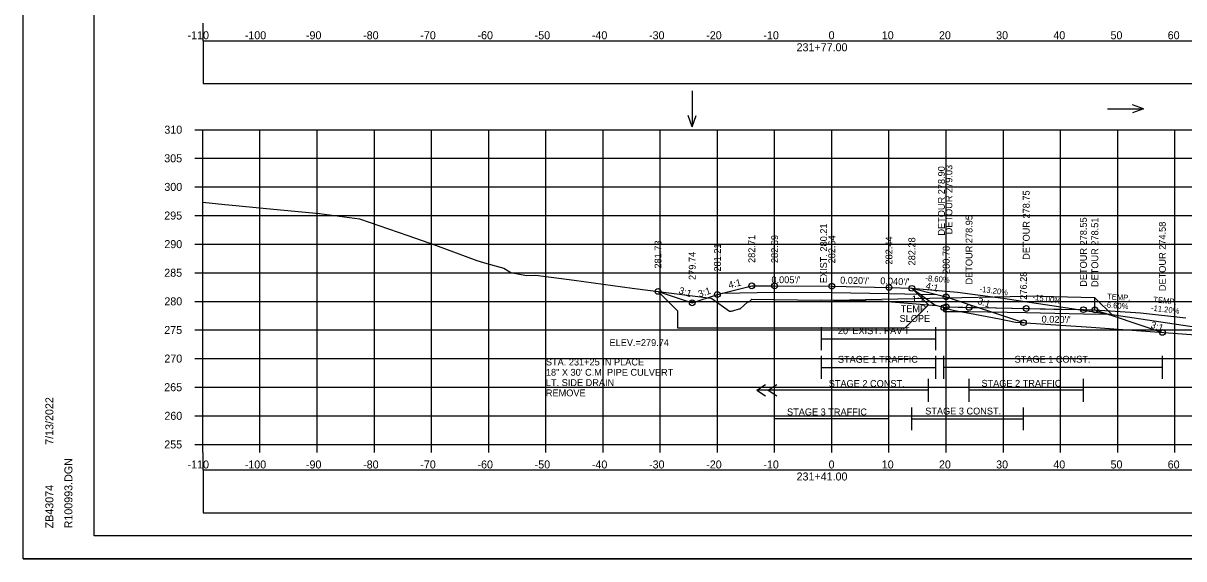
# Model space of a CAD drawing. Extents: x 4667 to 1632277, y -2100 to 724501.
# Drawn here: x 5635.8 to 5838.7, y 809.6 to 903.2 of the extents above; entities that cross this region are included whole.
import ezdxf

# ---------------------------------------------------------------- set-up
doc = ezdxf.new("R2010")
doc.units = 0
for name, color, linetype in [('R_Alt Surface', 7, 'Continuous'), ('R_Axis', 7, 'Continuous'), ('R_Axis Annot', 7, 'Continuous'), ('R_Border', 7, 'Continuous'), ('R_Border Notes', 7, 'Continuous'), ('R_Detour', 7, 'Continuous'), ('R_Detour Annot', 7, 'Continuous'), ('R_Drive', 7, 'Continuous'), ('R_Exist Surface', 7, 'Continuous'), ('R_Fin Surface', 7, 'Continuous'), ('R_Fin Surface Annot', 7, 'Continuous'), ('R_Grid', 7, 'Continuous'), ('R_No Plot', 7, 'Continuous'), ('R_Proposed CofA', 7, 'Continuous'), ('R_ROW', 7, 'Continuous'), ('R_Temp Easement', 7, 'Continuous'), ('R_Water Annot', 7, 'Continuous'), ('T_Drafting', 7, 'Continuous'), ('T_Notes', 7, 'Continuous')]:
    doc.layers.add(name, color=color, linetype=linetype)

msp = doc.modelspace()

# ---------------------------------------------------------------- linework, layer by layer
at = {"layer": 'R_Alt Surface'}
msp.add_lwpolyline([(5758.04, 856.03), (5767.18, 856.22), (5777.18, 856.17), (5787.18, 855.97), (5795.55, 855.8)], dxfattribs=at)
at = {"layer": 'R_Axis'}
for p, q in [((5665.78, 884.61), (5667.18, 884.61)), ((5667.18, 829.61), (5667.18, 884.61)), ((5665.78, 879.61), (5667.18, 879.61)), ((5665.78, 874.61), (5667.18, 874.61)), ((5665.78, 869.61), (5667.18, 869.61)), ((5665.78, 864.61), (5667.18, 864.61)), ((5665.78, 859.61), (5667.18, 859.61)), ((5665.78, 854.61), (5667.18, 854.61)), ((5665.78, 849.61), (5667.18, 849.61)), ((5665.78, 844.61), (5667.18, 844.61)), ((5665.78, 839.61), (5667.18, 839.61)), ((5665.78, 834.61), (5667.18, 834.61)), ((5665.78, 829.61), (5667.18, 829.61)), ((5667.18, 829.61), (5947.18, 829.61)), ((5667.18, 828.21), (5667.18, 829.61)), ((5677.18, 828.21), (5677.18, 829.61)), ((5687.18, 828.21), (5687.18, 829.61)), ((5697.18, 828.21), (5697.18, 829.61)), ((5707.18, 828.21), (5707.18, 829.61)), ((5717.18, 828.21), (5717.18, 829.61)), ((5727.18, 828.21), (5727.18, 829.61)), ((5737.18, 828.21), (5737.18, 829.61)), ((5747.18, 828.21), (5747.18, 829.61)), ((5757.18, 828.21), (5757.18, 829.61)), ((5767.18, 828.21), (5767.18, 829.61)), ((5777.18, 828.21), (5777.18, 829.61)), ((5787.18, 828.21), (5787.18, 829.61)), ((5797.18, 828.21), (5797.18, 829.61)), ((5807.18, 828.21), (5807.18, 829.61)), ((5817.18, 828.21), (5817.18, 829.61)), ((5827.18, 828.21), (5827.18, 829.61)), ((5837.18, 828.21), (5837.18, 829.61))]:
    msp.add_line(p, q, dxfattribs=at)
at = {"layer": 'R_Border'}
for p, q in [((5648.18, 813.61), (5648.18, 1019.07)), ((5648.18, 813.61), (5648.18, 813.61)), ((5964.36, 813.61), (5648.18, 813.61))]:
    msp.add_line(p, q, dxfattribs=at)
at = {"layer": 'R_Detour'}
for points in [[(5796.78, 852.84), (5796.78, 853.51), (5796.78, 853.51), (5796.78, 853.51), (5797.01, 853.59), (5797.18, 853.64), (5799.26, 853.6), (5801.18, 853.56), (5805.99, 853.47), (5811.18, 853.36), (5815.99, 853.27), (5821.18, 853.16), (5822.15, 853.15), (5823.18, 853.12), (5824.84, 852.57), (5826.38, 852.06), (5830.69, 850.62), (5834.99, 849.19)], [(5796.78, 852.84), (5801.17, 852.84), (5811.18, 852.64), (5821.17, 852.44), (5825.49, 852.36)]]:
    msp.add_lwpolyline(points, dxfattribs=at)
at = {"layer": 'R_Drive'}
for p, q in [((5791.18, 856.89), (5799.15, 856.2)), ((5799.15, 856.2), (5807.09, 855.16)), ((5807.09, 855.16), (5843.99, 849.62)), ((5823.18, 853.12), (5831.17, 852.6)), ((5831.17, 852.6), (5839.12, 851.71))]:
    msp.add_line(p, q, dxfattribs=at)
at = {"layer": 'R_Exist Surface'}
msp.add_lwpolyline([(5667.18, 871.94), (5671.03, 871.51), (5671.71, 871.49), (5678.32, 870.84), (5687.57, 869.98), (5694.6, 869.02), (5703.05, 866.11), (5707.86, 864.43), (5715.13, 861.76), (5716.87, 861.23), (5719.82, 860.39), (5721.04, 859.67), (5723.81, 859.12), (5725.43, 859.21), (5732.12, 858.29), (5742.29, 856.91), (5756.02, 855.17), (5756.21, 855.13), (5759.31, 852.91), (5759.33, 852.91), (5759.48, 852.92), (5759.56, 852.9), (5759.75, 852.97), (5759.88, 852.98), (5761, 853.29), (5761.15, 853.33), (5762.45, 854.44), (5762.72, 854.51), (5763.19, 855.02), (5775.13, 854.8), (5775.4, 854.85), (5779.71, 854.77), (5786.06, 854.65), (5786.15, 854.64), (5786.18, 854.62), (5791.23, 854.22), (5794.72, 853.96), (5795.36, 853.95), (5796.37, 853.63), (5796.66, 853.6), (5796.84, 853.49), (5798.65, 853.04), (5801.26, 852.54), (5806.5, 851.53), (5809.31, 850.98), (5822.54, 850.08), (5842.39, 848.66)], dxfattribs=at)
at = {"layer": 'R_Fin Surface'}
msp.add_lwpolyline([(5746.79, 856.34), (5752.77, 854.35), (5757.18, 855.82), (5758.04, 856.03), (5763.18, 857.32), (5767.18, 857.3), (5777.18, 857.25), (5787.18, 857.05), (5791.18, 856.89), (5795.55, 855.8), (5797.18, 855.39), (5810.69, 850.89)], dxfattribs=at)
at = {"layer": 'R_Grid'}
for p, q in [((5667.18, 884.61), (5947.18, 884.61)), ((5667.18, 829.61), (5667.18, 884.61)), ((5677.18, 829.61), (5677.18, 884.61)), ((5687.18, 829.61), (5687.18, 884.61)), ((5697.18, 829.61), (5697.18, 884.61)), ((5707.18, 829.61), (5707.18, 884.61)), ((5717.18, 829.61), (5717.18, 884.61)), ((5727.18, 829.61), (5727.18, 884.61)), ((5737.18, 829.61), (5737.18, 884.61)), ((5747.18, 829.61), (5747.18, 884.61)), ((5757.18, 829.61), (5757.18, 884.61)), ((5767.18, 829.61), (5767.18, 884.61)), ((5777.18, 829.61), (5777.18, 884.61)), ((5787.18, 829.61), (5787.18, 884.61)), ((5797.18, 829.61), (5797.18, 884.61)), ((5807.18, 829.61), (5807.18, 884.61)), ((5817.18, 829.61), (5817.18, 884.61)), ((5827.18, 829.61), (5827.18, 884.61)), ((5837.18, 829.61), (5837.18, 884.61)), ((5667.18, 879.61), (5947.18, 879.61)), ((5667.18, 874.61), (5947.18, 874.61)), ((5667.18, 869.61), (5947.18, 869.61)), ((5667.18, 864.61), (5947.18, 864.61)), ((5667.18, 859.61), (5947.18, 859.61)), ((5667.18, 854.61), (5947.18, 854.61)), ((5667.18, 849.61), (5947.18, 849.61)), ((5667.18, 844.61), (5947.18, 844.61)), ((5667.18, 839.61), (5947.18, 839.61)), ((5667.18, 834.61), (5947.18, 834.61)), ((5667.18, 829.61), (5947.18, 829.61))]:
    msp.add_line(p, q, dxfattribs=at)
at = {"layer": 'R_No Plot'}
for p, q in [((5667.18, 903.21), (5667.18, 900.14)), ((5791.18, 856.89), (5795.26, 853.95)), ((5667.18, 828.21), (5667.18, 825.14)), ((5635.78, 809.63), (5969.12, 809.63))]:
    msp.add_line(p, q, dxfattribs=at)
for points in [[(5635.78, 1022.97), (5969.12, 1022.97), (5969.12, 809.63), (5635.78, 809.63)], [(5882.1, 1019.07), (5901.72, 1019.07), (5901.72, 1009.19), (5917.84, 1009.19), (5941.04, 1009.19), (5941.04, 984.86), (5964.36, 984.86), (5964.36, 813.61), (5648.18, 813.61), (5648.18, 1019.07)]]:
    msp.add_lwpolyline(points, close=True, dxfattribs=at)
for centre in [(5746.79, 856.34), (5763.18, 857.32), (5767.18, 857.3), (5777.18, 857.25), (5787.18, 857.05), (5791.18, 856.89), (5752.77, 854.35), (5757.18, 855.82), (5797.18, 855.39), (5796.78, 853.51), (5797.18, 853.64), (5801.18, 853.56), (5811.18, 853.36), (5821.18, 853.16), (5823.18, 853.12), (5810.69, 850.89), (5834.99, 849.19)]:
    msp.add_circle(centre, 0.5, dxfattribs=at)
at = {"layer": 'R_Proposed CofA'}
for p, q in [((5764.07, 839.08), (5765.57, 840.08)), ((5764.07, 839.08), (5765.57, 838.08)), ((5766.07, 839.08), (5767.57, 840.08)), ((5766.07, 839.08), (5767.57, 838.08))]:
    msp.add_line(p, q, dxfattribs=at)
for points in [[(5667.23, 892.67), (5947.13, 892.67), (5947.13, 900.09), (5667.23, 900.09)], [(5667.23, 817.67), (5947.13, 817.67), (5947.13, 825.09), (5667.23, 825.09)]]:
    msp.add_lwpolyline(points, close=True, dxfattribs=at)
at = {"layer": 'R_ROW'}
for p, q in [((5746.79, 856.34), (5750.23, 852.9)), ((5750.27, 852.9), (5750.23, 852.9)), ((5750.27, 849.9), (5750.27, 852.9)), ((5794.07, 854.01), (5789.96, 849.9)), ((5789.96, 849.9), (5750.27, 849.9))]:
    msp.add_line(p, q, dxfattribs=at)
at = {"layer": 'R_Temp Easement'}
for p, q in [((5775.37, 846.08), (5775.37, 850.08)), ((5795.37, 846.08), (5795.37, 850.08)), ((5775.37, 848.08), (5795.37, 848.08)), ((5775.37, 841.08), (5775.37, 845.08)), ((5795.37, 841.08), (5795.37, 845.08)), ((5796.78, 841.08), (5796.78, 845.08)), ((5834.99, 841.08), (5834.99, 845.08)), ((5775.37, 843.08), (5795.37, 843.08)), ((5834.99, 843.08), (5796.78, 843.08)), ((5794.07, 837.08), (5794.07, 841.08)), ((5801.18, 837.08), (5801.18, 841.08)), ((5821.18, 837.08), (5821.18, 841.08)), ((5794.07, 839.08), (5764.07, 839.08)), ((5821.18, 839.08), (5801.18, 839.08)), ((5767.18, 832.08), (5767.18, 836.08)), ((5787.18, 832.08), (5787.18, 836.08)), ((5791.18, 832.08), (5791.18, 836.08)), ((5810.69, 832.08), (5810.69, 836.08)), ((5787.18, 834.08), (5767.18, 834.08)), ((5791.18, 834.08), (5810.69, 834.08))]:
    msp.add_line(p, q, dxfattribs=at)
at = {"layer": 'R_Water Annot'}
for p, q in [((5752.77, 891.42), (5752.77, 885.13)), ((5831.68, 888.27), (5829.75, 888.97)), ((5752.77, 885.13), (5752.07, 887.06)), ((5752.77, 885.13), (5753.47, 887.06)), ((5825.39, 888.27), (5831.68, 888.27)), ((5831.68, 888.27), (5829.75, 887.57))]:
    msp.add_line(p, q, dxfattribs=at)
at = {"layer": 'T_Drafting'}
msp.add_line((5791.18, 856.89), (5794.07, 854.01), dxfattribs=at)
at = {"layer": 'T_Notes'}
for p, q in [((5777.49, 854.81), (5811.18, 855.49)), ((5823.18, 855.25), (5811.18, 855.49)), ((5823.18, 853.12), (5823.18, 855.25)), ((5823.18, 855.25), (5826.37, 852.06)), ((5797.18, 853.64), (5823.18, 853.12)), ((5823.18, 853.12), (5826.37, 852.06))]:
    msp.add_line(p, q, dxfattribs=at)
msp.add_lwpolyline([(5777.49, 854.81), (5786.06, 854.65), (5786.15, 854.64), (5786.18, 854.62), (5791.23, 854.22), (5794.72, 853.96), (5795.36, 853.95), (5796.37, 853.63), (5796.66, 853.6), (5796.8, 853.52), (5797.18, 853.64)], dxfattribs=at)

# ---------------------------------------------------------------- texts
at = {"layer": 'R_Axis Annot'}
for s, p in [('-110', (5664.52, 900.41)), ('-100', (5674.52, 900.41)), ('-90', (5685.22, 900.41)), ('-80', (5695.22, 900.41)), ('-70', (5705.22, 900.41)), ('-60', (5715.22, 900.41)), ('-50', (5725.22, 900.41)), ('-40', (5735.22, 900.41)), ('-30', (5745.22, 900.41)), ('-20', (5755.22, 900.41)), ('-10', (5765.22, 900.41)), ('0', (5776.62, 900.41)), ('10', (5785.92, 900.41)), ('20', (5795.92, 900.41)), ('30', (5805.92, 900.41)), ('40', (5815.92, 900.41)), ('50', (5825.92, 900.41)), ('60', (5835.92, 900.41)), ('231+77.00', (5771.02, 898.31)), ('310', (5660.46, 883.91)), ('305', (5660.44, 878.91)), ('300', (5660.46, 873.91)), ('295', (5660.44, 868.91)), ('290', (5660.46, 863.91)), ('285', (5660.44, 858.91)), ('280', (5660.46, 853.91)), ('275', (5660.44, 848.91)), ('270', (5660.46, 843.91)), ('265', (5660.44, 838.91)), ('260', (5660.46, 833.91)), ('255', (5660.44, 828.91)), ('-110', (5664.52, 825.41)), ('-100', (5674.52, 825.41)), ('-90', (5685.22, 825.41)), ('-80', (5695.22, 825.41)), ('-70', (5705.22, 825.41)), ('-60', (5715.22, 825.41)), ('-50', (5725.22, 825.41)), ('-40', (5735.22, 825.41)), ('-30', (5745.22, 825.41)), ('-20', (5755.22, 825.41)), ('-10', (5765.22, 825.41)), ('0', (5776.62, 825.41)), ('10', (5785.92, 825.41)), ('20', (5795.92, 825.41)), ('30', (5805.92, 825.41)), ('40', (5815.92, 825.41)), ('50', (5825.92, 825.41)), ('60', (5835.92, 825.41)), ('231+41.00', (5771.02, 823.31))]:
    msp.add_text(s, height=1.4, dxfattribs=at).set_placement(p)
at = {"layer": 'R_Border'}
for s, p in [('7/13/2022', (5641.05, 829.54)), ('R100993.DGN', (5644.38, 814.94)), ('ZB43074', (5641.05, 814.94))]:
    msp.add_text(s, height=1.4, rotation=90, dxfattribs=at).set_placement(p)
at = {"layer": 'R_Border Notes'}
for s, p in [('1:1', (5791.16, 854.42)), ('TEMP.', (5789.22, 852.72)), ('SLOPE', (5789.03, 851.02))]:
    msp.add_text(s, height=1.2, dxfattribs=at).set_placement(p)
at = {"layer": 'R_Detour Annot'}
for s, rotation, p in [("0.020'/'", 358.8542, (5813.86, 850.91)), ('3:1', 341.5651, (5832.83, 850.03))]:
    msp.add_text(s, height=1.2, rotation=rotation, dxfattribs=at).set_placement(p)
at = {"layer": 'R_Drive'}
for s, rotation, p in [('-8.60%', 355.0847, (5793.52, 858.19)), ('-13.20%', 352.4804, (5802.98, 856.3)), ('-15.00%', 351.4668, (5812.25, 854.89)), ('-6.60%', 356.224, (5824.8, 853.52)), ('TEMP.', 356.224, (5825.29, 854.99)), ('TEMP.', 353.6095, (5833.36, 854.46)), ('-11.20%', 353.6095, (5832.97, 852.99))]:
    msp.add_text(s, height=1, rotation=rotation, dxfattribs=at).set_placement(p)
at = {"layer": 'R_Fin Surface Annot'}
for s, rotation, p in [('DETOUR 278.90', 90, (5796.95, 866.1)), ('DETOUR 279.03', 90, (5798.26, 866.33)), ('DETOUR 278.75', 90, (5811.78, 861.87)), ('DETOUR 278.95', 90, (5801.78, 857.56)), ('DETOUR 278.55', 90, (5821.78, 857.16)), ('DETOUR 278.51', 90, (5823.78, 857.12)), ('DETOUR 274.58', 90, (5835.59, 856.4)), ('281.73', 90, (5747.39, 860.34)), ('281.21', 90, (5757.78, 859.82)), ('282.71', 90, (5763.78, 861.32)), ('282.69', 90, (5767.78, 861.3)), ('282.64', 90, (5777.78, 861.25)), ('282.44', 90, (5787.78, 861.05)), ('282.28', 90, (5791.78, 860.89)), ('279.74', 90, (5753.37, 858.35)), ('280.78', 90, (5797.78, 859.39)), ("0.005'/'", 359.7141, (5766.62, 857.8)), ("0.020'/'", 358.8542, (5778.63, 857.72)), ("0.040'/'", 357.7094, (5785.64, 857.61)), ('276.28', 90, (5811.29, 854.89)), ('3:1', 341.5651, (5750.31, 856.04)), ('3:1', 18.4349, (5754.03, 855.29)), ('4:1', 14.0362, (5759.26, 856.85)), ('4:1', 345.9638, (5793.5, 856.83)), ('3:1', 341.5651, (5802.56, 854.2))]:
    msp.add_text(s, height=1.2, rotation=rotation, dxfattribs=at).set_placement(p)
at = {"layer": 'R_Temp Easement'}
msp.add_text('EXIST. 280.21', height=1.2, rotation=90, dxfattribs=at).set_placement((5776.34, 857.79))
for s, height, p in [("20' EXIST. PAV'T", 1.2, (5778.24, 848.88)), ('STAGE 1 TRAFFIC', 1.2, (5778.24, 843.88)), ('STAGE 1 CONST.', 1.1985, (5809.15, 843.89)), ('STAGE 2 CONST.', 1.1985, (5776.65, 839.65)), ('STAGE 2 TRAFFIC', 1.1985, (5803.35, 839.69)), ('STAGE 3 TRAFFIC', 1.1985, (5769.35, 834.69)), ('STAGE 3 CONST.', 1.1985, (5793.52, 834.84))]:
    msp.add_text(s, height=height, dxfattribs=at).set_placement(p)
at = {"layer": 'R_Water Annot'}
for s, p in [('ELEV.=279.74', (5738.31, 846.8)), ('STA. 231+25 IN PLACE', (5727.18, 843.41)), ('18" X 30\' C.M. PIPE CULVERT', (5727.18, 841.61)), ('LT. SIDE DRAIN', (5727.18, 839.81)), ('REMOVE', (5727.18, 838.01))]:
    msp.add_text(s, height=1.2, dxfattribs=at).set_placement(p)

doc.saveas('drawing.dxf')
